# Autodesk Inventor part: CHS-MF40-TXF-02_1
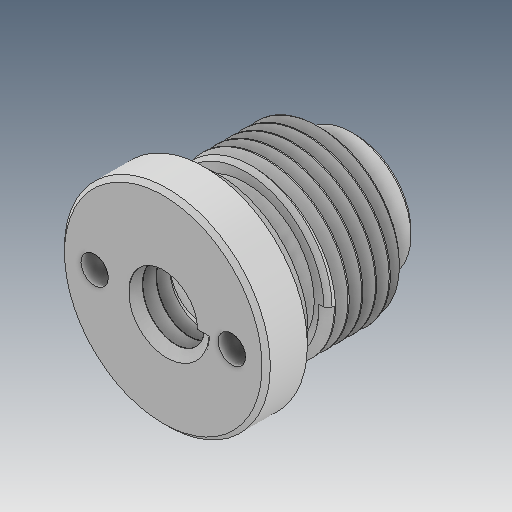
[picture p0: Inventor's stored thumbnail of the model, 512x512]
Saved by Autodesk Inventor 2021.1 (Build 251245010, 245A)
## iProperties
Created: 2019-04
Part Number: CHS-MF40-TXF-02_1
Material: Ogólny
Document SubType Name: Modeling
Designer: user
Density: 1 g/cm^3
Appearance: Domyślna
Author: user
Revision Number: ÈÎºÎ
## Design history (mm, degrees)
feature "ÊäÈë1"
node "Bryła1"
